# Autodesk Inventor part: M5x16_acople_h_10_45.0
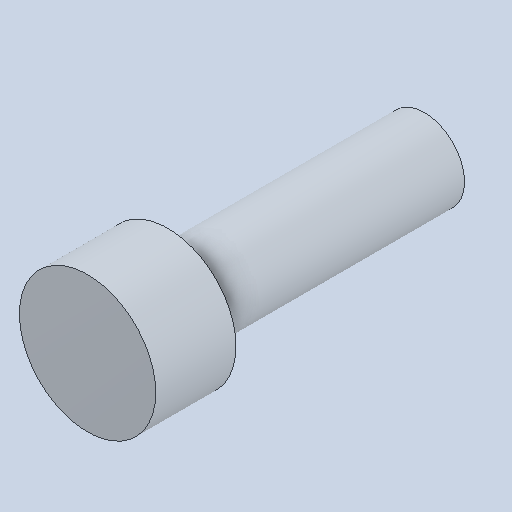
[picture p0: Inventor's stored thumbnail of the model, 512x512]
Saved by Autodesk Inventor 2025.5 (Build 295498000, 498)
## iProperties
Created: 2026-10
Part Number: M5x16_acople_h_10_45.0
Material: Genérico
Document SubType Name: Modeling
Designer: Luis M
Density: 1 g/cm^3
Appearance: Valor por defecto
Author: Luis M
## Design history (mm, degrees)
feature "Base1"
node "Sólido1"
